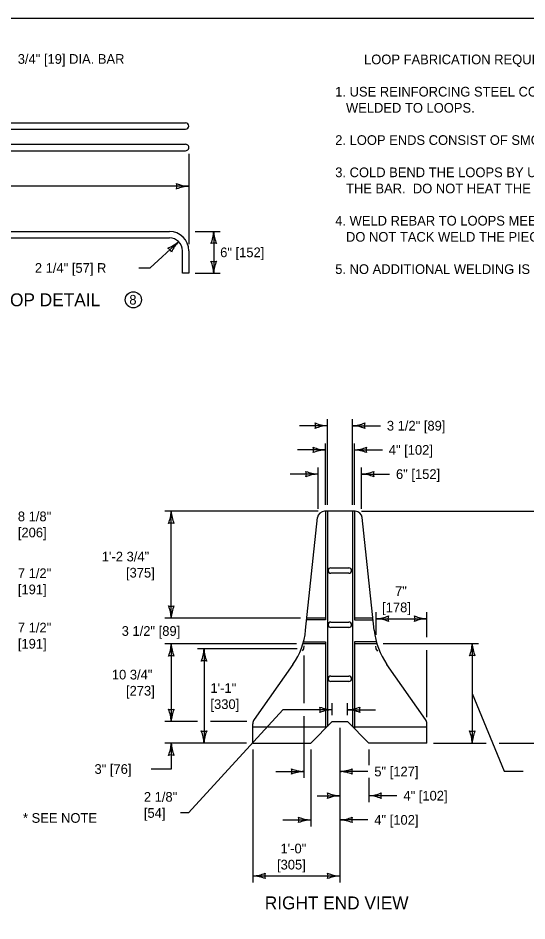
# Model space of a CAD drawing. Extents: x 49991.4 to 50021, y 49987.6 to 50011.4.
# Drawn here: x 50009.63 to 50012.78, y 49993.4 to 49999 of the extents above; entities that cross this region are included whole.
import ezdxf

# ---------------------------------------------------------------- set-up
doc = ezdxf.new("R2010")
doc.units = 0
for name, color, linetype in [('Level 1', 7, 'Continuous'), ('Level 2', 7, 'Continuous'), ('Level 3', 7, 'Continuous'), ('Level 4', 7, 'Continuous')]:
    doc.layers.add(name, color=color, linetype=linetype)

msp = doc.modelspace()

# ---------------------------------------------------------------- linework, layer by layer
at = {"layer": 'Level 1'}
for p, q in [((50008.376, 49998.3499), (50010.6665, 49998.3499)), ((50008.376, 49998.3098), (50010.6665, 49998.3098)), ((50008.3757, 49998.2169), (50010.6665, 49998.2169)), ((50008.5005, 49998.1767), (50010.6665, 49998.1767)), ((50008.3092, 49997.6768), (50010.5663, 49997.6768)), ((50008.3092, 49997.6367), (50010.5663, 49997.6367)), ((50010.6463, 49997.4168), (50010.6463, 49997.5567)), ((50010.6865, 49997.5567), (50010.6865, 49997.4168)), ((50010.6865, 49997.4168), (50010.6463, 49997.4168)), ((50011.411, 49995.2038), (50011.4847, 49995.9026)), ((50011.7181, 49995.9422), (50011.5287, 49995.9422)), ((50011.5335, 49995.9422), (50011.5335, 49995.2684)), ((50011.5455, 49995.9422), (50011.5455, 49994.6084)), ((50011.7012, 49995.9422), (50011.7012, 49994.6083)), ((50011.7131, 49995.9422), (50011.7131, 49995.2684)), ((50011.8357, 49995.2038), (50011.762, 49995.9026)), ((50011.5672, 49995.5911), (50011.6795, 49995.5911)), ((50011.6795, 49995.5575), (50011.5672, 49995.5575)), ((50011.5335, 49995.2796), (50011.419, 49995.2796)), ((50011.8277, 49995.2796), (50011.7131, 49995.2796)), ((50011.5335, 49995.2684), (50011.4178, 49995.2684)), ((50011.5672, 49995.255), (50011.6795, 49995.255)), ((50011.7131, 49995.2684), (50011.8289, 49995.2684)), ((50011.6795, 49995.2214), (50011.5672, 49995.2214)), ((50011.5335, 49995.1194), (50011.3938, 49995.1194)), ((50011.3972, 49995.1313), (50011.5335, 49995.1313)), ((50011.5335, 49995.1313), (50011.5335, 49994.5962)), ((50011.7131, 49995.1313), (50011.7131, 49994.5962)), ((50011.8495, 49995.1313), (50011.7131, 49995.1313)), ((50011.8529, 49995.1194), (50011.7131, 49995.1194)), ((50011.3318, 49994.9923), (50011.0919, 49994.6499)), ((50012.1548, 49994.65), (50011.9149, 49994.9923)), ((50011.5672, 49994.9203), (50011.6795, 49994.9203)), ((50011.6795, 49994.8866), (50011.5672, 49994.8866)), ((50011.0839, 49994.5042), (50011.0839, 49994.6246)), ((50011.4429, 49994.5042), (50011.5752, 49994.6386)), ((50011.5752, 49994.6386), (50011.6714, 49994.6386)), ((50011.8037, 49994.5042), (50011.6714, 49994.6386)), ((50012.1628, 49994.5042), (50012.1628, 49994.6246)), ((50011.0839, 49994.5042), (50011.4429, 49994.5042)), ((50012.1628, 49994.5042), (50011.8037, 49994.5042))]:
    msp.add_line(p, q, dxfattribs=at)
msp.add_lwpolyline([(49999.3835, 49998.9992), (50016.7501, 49998.9992), (50016.7501, 49987.7988), (49999.3835, 49987.7988)], close=True, dxfattribs=at)
for centre, radius, start, end in [((50010.6664, 49998.3299), 0.02, 270.2, 89.8), ((50010.6665, 49998.1968), 0.0201, 269.8823, 90.1177), ((50010.5655, 49997.5558), 0.121, 0.4343, 89.6039), ((50010.5663, 49997.5567), 0.08, 360, 90), ((50011.5287, 49995.8979), 0.0442, 90, 173.9725), ((50011.7181, 49995.8979), 0.0442, 6.0275, 90), ((50011.567, 49995.5743), 0.0168, 90, 270), ((50011.6794, 49995.5743), 0.0168, 270, 90), ((50011.567, 49995.2382), 0.0168, 90, 270), ((50011.6794, 49995.2382), 0.0168, 270, 90), ((50010.9624, 49995.2511), 0.451, 324.9777, 353.9725), ((50012.2843, 49995.2511), 0.451, 186.0275, 215.0223), ((50011.567, 49994.9034), 0.0168, 90, 270), ((50011.6794, 49994.9034), 0.0168, 270, 90), ((50011.1281, 49994.6246), 0.0442, 144.9777, 180), ((50012.1185, 49994.6246), 0.0442, 0, 35.0223)]:
    msp.add_arc(centre, radius, start, end, dxfattribs=at)
at = {"layer": 'Level 2'}
msp.add_circle((50010.3425, 49997.2528), 0.05, dxfattribs=at)
at = {"layer": 'Level 3'}
for p, q in [((50010.6865, 49998.1568), (50010.6865, 49997.5967)), ((50010.6865, 49997.9563), (50008.2892, 49997.9563)), ((50010.7265, 49997.6768), (50010.8808, 49997.6768)), ((50010.8408, 49997.6768), (50010.8408, 49997.4168)), ((50010.4477, 49997.4499), (50010.6231, 49997.613)), ((50010.3764, 49997.4499), (50010.4477, 49997.4499)), ((50010.7265, 49997.4168), (50010.8808, 49997.4168)), ((50011.5455, 49995.9822), (50011.5455, 49996.5122)), ((50011.7012, 49995.9822), (50011.7012, 49996.5122)), ((50011.5455, 49996.4722), (50011.372, 49996.4722)), ((50011.7012, 49996.4722), (50011.8746, 49996.4722)), ((50011.5335, 49995.9822), (50011.5335, 49996.3622)), ((50011.7131, 49995.9822), (50011.7131, 49996.3622)), ((50011.5335, 49996.3222), (50011.36, 49996.3222)), ((50011.7131, 49996.3222), (50011.8865, 49996.3222)), ((50011.4889, 49995.9574), (50011.4889, 49996.2122)), ((50011.7578, 49995.9574), (50011.7578, 49996.2122)), ((50011.4889, 49996.1722), (50011.3154, 49996.1722)), ((50011.7578, 49996.1722), (50011.9312, 49996.1722)), ((50011.4887, 49995.9422), (50010.5373, 49995.9422)), ((50010.5773, 49995.2796), (50010.5773, 49995.9422)), ((50011.7581, 49995.9422), (50012.9459, 49995.9422)), ((50011.379, 49995.2796), (50010.5373, 49995.2796)), ((50011.848, 49995.1767), (50011.848, 49995.3159)), ((50012.1628, 49995.1613), (50012.1628, 49995.3159)), ((50011.848, 49995.2759), (50012.1628, 49995.2759)), ((50011.4098, 49995.1942), (50011.4098, 49995.1942)), ((50011.3538, 49995.1194), (50010.5373, 49995.1194)), ((50010.5773, 49995.1194), (50010.5773, 49994.6386)), ((50011.8923, 49995.1213), (50012.4838, 49995.1213)), ((50012.4438, 49995.1213), (50012.4438, 49994.5042)), ((50011.3587, 49995.088), (50010.7407, 49995.088)), ((50010.7807, 49995.088), (50010.7807, 49994.5042)), ((50011.391, 49995.0771), (50011.3987, 49995.088)), ((50011.3987, 49995.088), (50011.4007, 49995.107)), ((50011.8479, 49995.088), (50011.846, 49995.1056)), ((50011.8577, 49995.0739), (50011.8479, 49995.088)), ((50012.1628, 49994.6646), (50012.1628, 49995.0813)), ((50011.3987, 49995.048), (50011.3987, 49994.7515)), ((50011.5752, 49994.6786), (50011.5752, 49994.7515)), ((50011.6714, 49994.6786), (50011.6714, 49994.7515)), ((50011.3987, 49994.6715), (50011.3987, 49994.2885)), ((50011.6714, 49994.7115), (50011.8448, 49994.7115)), ((50010.7407, 49994.6386), (50010.5373, 49994.6386)), ((50011.0459, 49994.6386), (50010.8207, 49994.6386)), ((50011.6233, 49994.5986), (50011.6233, 49993.6411)), ((50011.0439, 49994.5042), (50010.5374, 49994.5042)), ((50010.5773, 49994.5042), (50010.5773, 49994.3438)), ((50011.4429, 49994.5042), (50011.4429, 49994.5042)), ((50011.4429, 49994.5042), (50011.4429, 49994.5042)), ((50012.1628, 49994.5042), (50012.1628, 49994.5042)), ((50012.1628, 49994.5042), (50012.1628, 49994.5042)), ((50012.1628, 49994.5042), (50012.1628, 49994.5042)), ((50012.2028, 49994.5042), (50012.5307, 49994.5042)), ((50012.6107, 49994.5042), (50012.9459, 49994.5042)), ((50011.0838, 49994.4642), (50011.0838, 49993.6411)), ((50011.4429, 49994.4642), (50011.4429, 49993.9885)), ((50011.8037, 49994.4642), (50011.8037, 49994.3685)), ((50010.5773, 49994.3438), (50010.4526, 49994.3438)), ((50011.2252, 49994.3285), (50011.3987, 49994.3285)), ((50011.7967, 49994.3285), (50011.6233, 49994.3285)), ((50011.8037, 49994.2885), (50011.8037, 49994.1385)), ((50011.4829, 49994.1785), (50011.6233, 49994.1785)), ((50011.9771, 49994.1785), (50011.8037, 49994.1785)), ((50011.2694, 49994.0285), (50011.4429, 49994.0285)), ((50011.7967, 49994.0285), (50011.6233, 49994.0285)), ((50011.0838, 49993.6811), (50011.6233, 49993.6811))]:
    msp.add_line(p, q, dxfattribs=at)
for points in [[(50012.4438, 49994.8127), (50012.6423, 49994.3301), (50012.7604, 49994.3301)], [(50011.5752, 49994.7115), (50011.2684, 49994.7115), (50010.6844, 49994.0713), (50010.6342, 49994.0713)]]:
    msp.add_lwpolyline(points, dxfattribs=at)
for centre, radius, start, end in [((50010.6956, 49998.1784), 0.2223, 247.456, 267.6395), ((50010.5582, 49997.9563), 0.0548, 342.1388, 17.8612), ((50010.6979, 49997.7236), 0.233, 92.8273, 112.0772), ((50010.6186, 49997.686), 0.2223, 337.456, 357.6395), ((50011.0735, 49997.6883), 0.233, 182.8273, 202.0772), ((50010.4786, 49997.782), 0.2223, 290.37, 310.5535), ((50010.5292, 49997.5257), 0.0548, 25.0528, 60.7752), ((50010.79, 49997.4504), 0.233, 135.7413, 154.9912), ((50010.8408, 49997.5486), 0.0548, 72.1388, 107.8612), ((50010.8408, 49997.545), 0.0548, 252.1388, 287.8612), ((50010.608, 49997.4053), 0.233, 2.8273, 22.0772), ((50011.0629, 49997.4076), 0.2223, 157.456, 177.6395), ((50011.5546, 49996.6943), 0.2223, 247.456, 267.6395), ((50011.4173, 49996.4722), 0.0548, 342.1388, 17.8612), ((50011.557, 49996.2395), 0.233, 92.8273, 112.0772), ((50011.6897, 49996.7049), 0.233, 272.8273, 292.0772), ((50011.692, 49996.25), 0.2223, 67.456, 87.6395), ((50011.8294, 49996.4722), 0.0548, 162.1388, 197.8612), ((50011.5426, 49996.5443), 0.2223, 247.456, 267.6395), ((50011.4053, 49996.3222), 0.0548, 342.1388, 17.8612), ((50011.545, 49996.0895), 0.233, 92.8273, 112.0772), ((50011.7016, 49996.5549), 0.233, 272.8273, 292.0772), ((50011.7039, 49996.1), 0.2223, 67.456, 87.6395), ((50011.8413, 49996.3222), 0.0548, 162.1388, 197.8612), ((50011.498, 49996.3943), 0.2223, 247.456, 267.6395), ((50011.3607, 49996.1722), 0.0548, 342.1388, 17.8612), ((50011.7463, 49996.4049), 0.233, 272.8273, 292.0772), ((50011.886, 49996.1722), 0.0548, 162.1388, 197.8612), ((50011.5004, 49995.9395), 0.233, 92.8273, 112.0772), ((50011.7486, 49995.95), 0.2223, 67.456, 87.6395), ((50010.3551, 49995.9514), 0.2223, 337.456, 357.6395), ((50010.81, 49995.9537), 0.233, 182.8273, 202.0772), ((50010.5773, 49995.814), 0.0548, 72.1388, 107.8612), ((50010.5773, 49995.4078), 0.0548, 252.1388, 287.8612), ((50010.3446, 49995.2681), 0.233, 2.8273, 22.0772), ((50010.7994, 49995.2705), 0.2223, 157.456, 177.6395), ((50011.8365, 49995.5086), 0.233, 272.8273, 292.0772), ((50011.9762, 49995.2759), 0.0548, 162.1388, 197.8612), ((50012.1719, 49995.498), 0.2223, 247.456, 267.6395), ((50012.0346, 49995.2759), 0.0548, 342.1388, 17.8612), ((50011.8388, 49995.0537), 0.2223, 67.456, 87.6395), ((50012.1743, 49995.0432), 0.233, 92.8273, 112.0772), ((50010.3551, 49995.1285), 0.2223, 337.456, 357.6395), ((50010.81, 49995.1309), 0.233, 182.8273, 202.0772), ((50012.2216, 49995.1304), 0.2223, 337.456, 357.6395), ((50012.6765, 49995.1328), 0.233, 182.8273, 202.0772), ((50010.5586, 49995.0971), 0.2223, 337.456, 357.6395), ((50011.0134, 49995.0995), 0.233, 182.8273, 202.0772), ((50010.5773, 49994.9912), 0.0548, 72.1388, 107.8612), ((50010.7807, 49994.9598), 0.0548, 72.1388, 107.8612), ((50012.4438, 49994.9931), 0.0548, 72.1388, 107.8612), ((50011.5843, 49994.9336), 0.2223, 247.456, 267.6395), ((50011.447, 49994.7115), 0.0548, 342.1388, 17.8612), ((50011.6599, 49994.9442), 0.233, 272.8273, 292.0772), ((50011.7996, 49994.7115), 0.0548, 162.1388, 197.8612), ((50010.5773, 49994.7668), 0.0548, 252.1388, 287.8612), ((50010.3446, 49994.6271), 0.233, 2.8273, 22.0772), ((50010.7994, 49994.6294), 0.2223, 157.456, 177.6395), ((50011.5867, 49994.4788), 0.233, 92.8273, 112.0772), ((50011.6622, 49994.4893), 0.2223, 67.456, 87.6395), ((50010.7807, 49994.6324), 0.0548, 252.1388, 287.8612), ((50010.548, 49994.4927), 0.233, 2.8273, 22.0772), ((50011.0028, 49994.4951), 0.2223, 157.456, 177.6395), ((50012.4438, 49994.6324), 0.0548, 252.1388, 287.8612), ((50012.2111, 49994.4927), 0.233, 2.8273, 22.0772), ((50012.6659, 49994.495), 0.2223, 157.456, 177.6395), ((50010.3447, 49994.5157), 0.233, 337.9228, 357.1727), ((50010.7995, 49994.5134), 0.2223, 182.3605, 202.544), ((50010.5774, 49994.376), 0.0548, 72.1388, 107.8612), ((50011.4078, 49994.5506), 0.2223, 247.456, 267.6395), ((50011.2705, 49994.3285), 0.0548, 342.1388, 17.8612), ((50011.4102, 49994.0958), 0.233, 92.8273, 112.0772), ((50011.6118, 49994.5612), 0.233, 272.8273, 292.0772), ((50011.6141, 49994.1063), 0.2223, 67.456, 87.6395), ((50011.7515, 49994.3285), 0.0548, 162.1388, 197.8612), ((50011.6324, 49994.4006), 0.2223, 247.456, 267.6395), ((50011.4951, 49994.1785), 0.0548, 342.1388, 17.8612), ((50011.6348, 49993.9458), 0.233, 92.8273, 112.0772), ((50011.7922, 49994.4112), 0.233, 272.8273, 292.0772), ((50011.7945, 49993.9563), 0.2223, 67.456, 87.6395), ((50011.9319, 49994.1785), 0.0548, 162.1388, 197.8612), ((50011.452, 49994.2506), 0.2223, 247.456, 267.6395), ((50011.3147, 49994.0285), 0.0548, 342.1388, 17.8612), ((50011.4544, 49993.7958), 0.233, 92.8273, 112.0772), ((50011.6118, 49994.2612), 0.233, 272.8273, 292.0772), ((50011.6141, 49993.8063), 0.2223, 67.456, 87.6395), ((50011.7515, 49994.0285), 0.0548, 162.1388, 197.8612), ((50011.0723, 49993.9138), 0.233, 272.8273, 292.0772), ((50011.0746, 49993.4589), 0.2223, 67.456, 87.6395), ((50011.212, 49993.6811), 0.0548, 162.1388, 197.8612), ((50011.6324, 49993.9032), 0.2223, 247.456, 267.6395), ((50011.4951, 49993.6811), 0.0548, 342.1388, 17.8612), ((50011.6348, 49993.4484), 0.233, 92.8273, 112.0772)]:
    msp.add_arc(centre, radius, start, end, dxfattribs=at)
at = {"layer": 'Level 4'}
for p, q in [((50011.0839, 49994.605), (50011.5421, 49994.605)), ((50011.7044, 49994.605), (50012.1628, 49994.605))]:
    msp.add_line(p, q, dxfattribs=at)

# ---------------------------------------------------------------- texts
at = {"layer": 'Level 2'}
msp.add_text('3/4" [19] DIA. BAR', height=0.06, rotation=360, dxfattribs=at).set_placement((50009.6256, 49998.7157))
for s, height, p in [('LOOP FABRICATION REQUIREMENTS', 0.06, (50011.7732, 49998.7128)), ('1. USE REINFORCING STEEL CONFORMING TO ASTM A 706 [706M], GRADE 60 [420] FOR REBAR BEING ', 0.06, (50011.5943, 49998.5128)), ('   WELDED TO LOOPS.', 0.06, (50011.5943, 49998.4128)), ('2. LOOP ENDS CONSIST OF SMOOTH ROUND BARS CONFORMING TO AASHTO M 270 [270M], GRADE 36 [250].', 0.06, (50011.5943, 49998.2128)), ('3. COLD BEND THE LOOPS BY USING A JIG THAT WILL PRODUCE AN ACCURATE RADIUS WITHOUT MARRING', 0.06, (50011.5943, 49998.0128)), ('   THE BAR.  DO NOT HEAT THE BAR TO FACILITATE BENDING.', 0.06, (50011.5943, 49997.9128)), ('4. WELD REBAR TO LOOPS MEETING SECTION 556 REQUIREMENTS USING 1/8" [3]  DIA. E8018 ROD.', 0.06, (50011.5943, 49997.7128)), ('   DO NOT TACK WELD THE PIECES TOGETHER PRIOR TO WELDING.', 0.06, (50011.5943, 49997.6128)), ('6" [152]', 0.06, (50010.8808, 49997.5168)), ('2 1/4" [57] R', 0.06, (50009.7318, 49997.4199)), ('5. NO ADDITIONAL WELDING IS PERMITTED ON THE SMOOTH ROUND BARS OR REINFORCING STEEL.', 0.06, (50011.5943, 49997.4128)), ('OPTIONAL LOOP DETAIL', 0.08, (50008.8643, 49997.2126)), ('8', 0.06, (50010.3175, 49997.2228)), ('3 1/2" [89]', 0.06, (50011.9146, 49996.4422)), ('4" [102]', 0.06, (50011.9265, 49996.2922)), ('6" [152]', 0.06, (50011.9712, 49996.1422)), ('8 1/8"', 0.06, (50009.6262, 49995.88)), ('[206]', 0.06, (50009.6262, 49995.78)), ('1\'-2 3/4"', 0.06, (50010.1469, 49995.6309)), ('7 1/2"', 0.06, (50009.6262, 49995.5275)), ('[375]', 0.06, (50010.2968, 49995.5309)), ('[191]', 0.06, (50009.6262, 49995.4275)), ('7"', 0.06, (50011.9651, 49995.4159)), ('[178]', 0.06, (50011.8852, 49995.3159)), ('7 1/2"', 0.06, (50009.6262, 49995.1906)), ('3 1/2" [89]', 0.06, (50010.2702, 49995.1695)), ('[191]', 0.06, (50009.6262, 49995.0906)), ('10 3/4"', 0.06, (50010.2092, 49994.899)), ('[273]', 0.06, (50010.2968, 49994.799)), ('1\'-1"', 0.06, (50010.8207, 49994.8161)), ('[330]', 0.06, (50010.8207, 49994.7161)), ('3" [76]', 0.06, (50010.1015, 49994.3138)), ('5" [127]', 0.06, (50011.8367, 49994.2985)), ('2 1/8"', 0.06, (50010.4077, 49994.1413)), ('4" [102]', 0.06, (50012.0171, 49994.1485)), ('[54]', 0.06, (50010.4077, 49994.0413)), ('* SEE NOTE', 0.06, (50009.658, 49994.0105)), ('4" [102]', 0.06, (50011.8367, 49993.9985)), ('1\'-0"', 0.06, (50011.2551, 49993.8211)), ('[305]', 0.06, (50011.2333, 49993.7211)), ('RIGHT END VIEW', 0.08, (50011.1575, 49993.474))]:
    msp.add_text(s, height=height, dxfattribs=at).set_placement(p)

doc.saveas('drawing.dxf')
